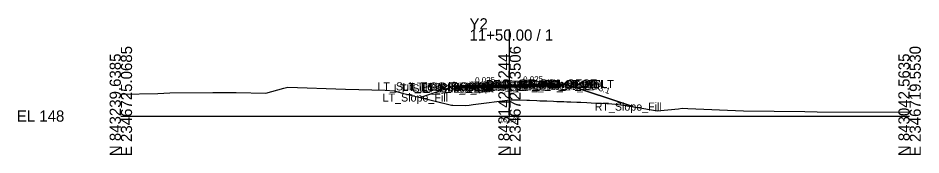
# Model space of a CAD drawing. Extents: x -26 to 2346977, y -10 to 843253.
# Drawn here: x -25.7 to 200, y 990.3 to 1024.5 of the extents above; entities that cross this region are included whole.
import ezdxf

# ---------------------------------------------------------------- set-up
doc = ezdxf.new("R2010")
doc.units = 0
for name, color, linetype in [('Default', 7, 'Continuous'), ('Exist Cross Section Cell', 7, 'Continuous'), ('Exist XS Center Line Elevation Label', 7, 'Continuous'), ('Exist XS Ground Line', 7, 'Continuous'), ('Prop CMT Pvmt Course 1', 7, 'Continuous'), ('Prop CMT Pvmt Course 2', 7, 'Continuous'), ('Prop CMT Pvmt Course 3', 7, 'Continuous'), ('Prop CMT Pvmt Surface', 7, 'Continuous'), ('Prop CMT Pvmt Surface Shoulder', 7, 'Continuous'), ('Prop CMT Shld Paved Course 1', 7, 'Continuous'), ('Prop CMT Shld Paved Course 2', 7, 'Continuous'), ('Prop CMT Shld Paved Course 3', 7, 'Continuous'), ('Prop CMT Slope Grass', 7, 'Continuous'), ('Prop CMT Subgrade Earthwork', 7, 'Continuous'), ('Prop XS Earthwork Shape', 7, 'Continuous'), ('Prop XS SE Text', 7, 'Continuous'), ('Prop XS Side Slope Text', 7, 'Continuous'), ('Scratch_Level_2', 7, 'Continuous')]:
    doc.layers.add(name, color=color, linetype=linetype)

msp = doc.modelspace()

# ---------------------------------------------------------------- linework, layer by layer
at = {"layer": 'Exist Cross Section Cell'}
for p, q in [((97.15, 1000), (97.15, 1021.61)), ((0, 1000), (97.15, 1000)), ((97.15, 1000), (197.15, 1000))]:
    msp.add_line(p, q, dxfattribs=at)
at = {"layer": 'Exist XS Ground Line'}
msp.add_lwpolyline([(0, 1005.45), (9.25, 1005.66), (12.21, 1005.79), (23.01, 1005.84), (25.23, 1005.85), (28.42, 1005.86), (28.84, 1005.85), (36.24, 1005.74), (40.77, 1006.94), (41.76, 1007.2), (56.12, 1006.7), (66.04, 1006.43), (68.3, 1006.28), (70.38, 1005.71), (82.67, 1002.74), (83.01, 1002.73), (86.27, 1002.64), (87.06, 1002.74), (88.1, 1002.87), (97.3, 1004.09), (98.05, 1004.08), (99.01, 1004.04), (99.61, 1004.02), (101.5, 1003.96), (102.18, 1003.93), (104, 1003.87), (104.77, 1003.84), (106.52, 1003.77), (108.15, 1003.71), (109.01, 1003.67), (110.05, 1003.64), (110.35, 1003.63), (110.77, 1003.61), (111.48, 1003.58), (112.44, 1003.54), (113.96, 1003.47), (115, 1003.43), (116.48, 1003.37), (117.58, 1003.31), (118.99, 1003.24), (120.17, 1003.19), (121.48, 1003.12), (122.76, 1003.02), (123.65, 1002.98), (124.94, 1002.8), (127.61, 1002.42), (130.75, 1001.93), (134.09, 1001.33), (139.37, 1001.84), (140.31, 1001.94), (141.72, 1001.88), (155.66, 1001.33), (171, 1001.14), (174.07, 1001.09), (197.15, 1000.98)], dxfattribs=at)
at = {"layer": 'Prop CMT Pvmt Course 1'}
for p, q in [((97.15, 1007.83), (85.15, 1007.53)), ((85.15, 1007.28), (97.15, 1007.58)), ((85.15, 1007.53), (85.15, 1007.28)), ((97.15, 1007.83), (109.15, 1008.13)), ((109.15, 1007.88), (97.15, 1007.58)), ((97.15, 1007.58), (97.15, 1007.83)), ((97.15, 1007.58), (97.15, 1007.83)), ((97.15, 1007.58), (97.15, 1007.7)), ((97.15, 1007.7), (97.15, 1007.7)), ((97.15, 1007.7), (97.15, 1007.58)), ((97.15, 1007.58), (97.15, 1007.7)), ((97.15, 1007.7), (97.15, 1007.7)), ((97.15, 1007.7), (97.15, 1007.58)), ((97.15, 1007.58), (97.15, 1007.58)), ((97.15, 1007.58), (97.15, 1007.58)), ((109.15, 1008.13), (109.15, 1007.88))]:
    msp.add_line(p, q, dxfattribs=at)
at = {"layer": 'Prop CMT Pvmt Course 2'}
for p, q in [((85.15, 1007.28), (97.15, 1007.58)), ((97.15, 1007.58), (85.15, 1007.28)), ((85.15, 1007.28), (85.15, 1007.28)), ((109.15, 1007.88), (97.15, 1007.58)), ((97.15, 1007.58), (109.15, 1007.88)), ((97.15, 1007.58), (97.15, 1007.58)), ((97.15, 1007.58), (97.15, 1007.58)), ((109.15, 1007.88), (109.15, 1007.88))]:
    msp.add_line(p, q, dxfattribs=at)
at = {"layer": 'Prop CMT Pvmt Course 3'}
for p, q in [((97.15, 1007.58), (85.15, 1007.28)), ((85.15, 1007.28), (85.15, 1006.94)), ((85.15, 1006.94), (97.15, 1007.24)), ((97.15, 1007.58), (109.15, 1007.88)), ((97.15, 1007.24), (97.15, 1007.58)), ((97.15, 1007.24), (97.15, 1007.58)), ((109.15, 1007.54), (97.15, 1007.24)), ((109.15, 1007.88), (109.15, 1007.54))]:
    msp.add_line(p, q, dxfattribs=at)
at = {"layer": 'Prop CMT Pvmt Surface'}
for q in [(85.15, 1007.53), (109.15, 1008.13)]:
    msp.add_line((97.15, 1007.83), q, dxfattribs=at)
at = {"layer": 'Prop CMT Pvmt Surface Shoulder'}
for p, q in [((85.15, 1007.53), (85.15, 1007.53)), ((109.15, 1008.13), (109.15, 1008.13))]:
    msp.add_line(p, q, dxfattribs=at)
at = {"layer": 'Prop CMT Shld Paved Course 1'}
for p, q in [((85.15, 1007.53), (84.9, 1007.27)), ((84.9, 1007.27), (85.15, 1007.28)), ((85.15, 1007.53), (85.15, 1007.53)), ((85.15, 1007.28), (85.15, 1007.53)), ((109.15, 1008.13), (109.15, 1008.13)), ((109.15, 1008.13), (109.41, 1007.87)), ((109.15, 1007.88), (109.15, 1008.13)), ((109.41, 1007.87), (109.15, 1007.88))]:
    msp.add_line(p, q, dxfattribs=at)
at = {"layer": 'Prop CMT Shld Paved Course 2'}
for p, q in [((85.15, 1007.28), (84.9, 1007.27)), ((84.9, 1007.27), (85.15, 1007.28)), ((84.9, 1007.27), (84.9, 1007.27)), ((85.15, 1007.28), (85.15, 1007.28)), ((109.15, 1007.88), (109.41, 1007.87)), ((109.41, 1007.87), (109.15, 1007.88)), ((109.15, 1007.88), (109.15, 1007.88)), ((109.41, 1007.87), (109.41, 1007.87))]:
    msp.add_line(p, q, dxfattribs=at)
at = {"layer": 'Prop CMT Shld Paved Course 3'}
for p, q in [((84.4, 1007.26), (84.06, 1006.92)), ((84.06, 1006.92), (85.15, 1006.94)), ((84.9, 1007.27), (84.4, 1007.26)), ((85.15, 1007.28), (84.9, 1007.27)), ((85.15, 1006.94), (85.15, 1007.28)), ((109.15, 1007.88), (109.41, 1007.87)), ((109.15, 1007.54), (109.15, 1007.88)), ((110.25, 1007.52), (109.15, 1007.54)), ((109.41, 1007.87), (109.91, 1007.86)), ((109.91, 1007.86), (110.25, 1007.52))]:
    msp.add_line(p, q, dxfattribs=at)
at = {"layer": 'Prop CMT Slope Grass'}
for p, q in [((83.15, 1007.37), (74.91, 1004.62)), ((85.15, 1007.53), (83.15, 1007.37)), ((109.15, 1008.13), (111.15, 1007.97)), ((111.15, 1007.97), (127.96, 1002.36))]:
    msp.add_line(p, q, dxfattribs=at)
at = {"layer": 'Prop CMT Subgrade Earthwork'}
for p, q in [((84.06, 1006.92), (83.58, 1007.4)), ((85.15, 1006.94), (84.06, 1006.92)), ((97.15, 1007.24), (85.15, 1006.94)), ((97.15, 1007.24), (109.15, 1007.54)), ((109.15, 1007.54), (110.25, 1007.52)), ((110.25, 1007.52), (110.73, 1008))]:
    msp.add_line(p, q, dxfattribs=at)
at = {"layer": 'Prop XS Earthwork Shape'}
msp.add_lwpolyline([(84.06, 1006.92), (83.58, 1007.4), (83.15, 1007.37), (74.91, 1004.62), (82.67, 1002.74), (83.01, 1002.73), (86.27, 1002.64), (87.06, 1002.74), (88.1, 1002.87), (97.3, 1004.09), (98.05, 1004.08), (99.01, 1004.04), (99.61, 1004.02), (101.5, 1003.96), (102.18, 1003.93), (104, 1003.87), (104.77, 1003.84), (106.52, 1003.77), (108.15, 1003.71), (109.01, 1003.67), (110.05, 1003.64), (110.35, 1003.63), (110.77, 1003.61), (111.48, 1003.58), (112.44, 1003.54), (113.96, 1003.47), (115, 1003.43), (116.48, 1003.37), (117.58, 1003.31), (118.99, 1003.24), (120.17, 1003.19), (121.48, 1003.12), (122.76, 1003.02), (123.65, 1002.98), (124.94, 1002.8), (127.61, 1002.42), (127.96, 1002.36), (111.15, 1007.97), (110.73, 1008), (110.25, 1007.52), (109.15, 1007.54), (97.15, 1007.24), (85.15, 1006.94)], close=True, dxfattribs=at)

# ---------------------------------------------------------------- texts
at = {"layer": 'Default'}
msp.add_text('-', height=0.0001, dxfattribs=at).set_placement((0, 1000))
at = {"layer": 'Exist Cross Section Cell'}
for s, p in [('Y2', (87.15, 1021.61)), ('11+50.00 / 1', (87.15, 1018.81)), ('EL 148', (-26, 998.6))]:
    msp.add_text(s, height=2.8, dxfattribs=at).set_placement(p)
for s, p in [('E 2346725.0685', (2.8, 990)), ('E 2346722.3506', (99.95, 990)), ('E 2346719.5530', (199.95, 990)), ('N 843239.6385', (0, 990)), ('N 843142.5244', (97.15, 990)), ('N 843042.5635', (197.15, 990))]:
    msp.add_text(s, height=2.8, rotation=90, dxfattribs=at).set_placement(p)
at = {"layer": 'Exist XS Center Line Elevation Label'}
msp.add_text('152.07', height=1.2, dxfattribs=at).set_placement((94.66, 998.47))
at = {"layer": 'Prop XS SE Text'}
for p in [(88.57, 1008.17), (100.57, 1008.37)]:
    msp.add_text('0.025', height=1.5, rotation=1.4321, dxfattribs=at).set_placement(p)
at = {"layer": 'Prop XS Side Slope Text'}
for rotation, p in [(18.4332, (78.48, 1006.1)), (341.5668, (119.34, 1006.37))]:
    msp.add_text('3:1', height=1.5, rotation=rotation, dxfattribs=at).set_placement(p)
at = {"layer": 'Scratch_Level_2'}
for s, p in [('RT_Sub_Trench_Out_DLT', (91.25, 1007)), ('PV1_PGL', (91.62, 1006.83)), ('RT_PS3_Shelf_Out', (95.84, 1006.86)), ('RT_PV3_OEOT', (99.28, 1006.88)), ('RT_PV2_OEOT', (99.28, 1006.88)), ('RT_PS3_OEOP', (99.6, 1006.87)), ('RT_PS2_OEOP', (99.6, 1006.87)), ('RT_PV1_OEOT', (99.85, 1007.13)), ('RT_PS1_OEOP', (99.91, 1007.13)), ('RT_GS_OS_CTL', (100.48, 1006.97)), ('LT_Sub_Trench_Out_DLT', (64.14, 1006.4)), ('LT_Sub_Trench_Out', (68.26, 1005.92)), ('LT_PS3_Shelf_Out', (70.38, 1006.26)), ('LT_GS_OS_CTL', (72.52, 1006.37)), ('LT_PS3_OEOP', (75.13, 1006.27)), ('LT_PS2_OEOP', (75.13, 1006.27)), ('LT_Sub_OEOT', (75.23, 1005.94)), ('LT_PV3_OEOT', (75.33, 1006.28)), ('LT_PV2_OEOT', (75.33, 1006.28)), ('LT_PV1_OEOT', (75.89, 1006.53)), ('LT_PS1_OEOP', (75.96, 1006.53)), ('RT_Sub_OEEOP', (86.32, 1006.24)), ('LT_Sub_OEEOP', (86.36, 1006.24)), ('RT_PV2_OEEOP', (86.41, 1006.58)), ('RT_PV3_OEEOP', (86.41, 1006.58)), ('LT_PV2_OEEOP', (86.46, 1006.58)), ('LT_PV3_OEEOP', (86.46, 1006.58)), ('RT_PV1_OEEOP', (86.98, 1006.7)), ('LT_PV1_OEEOP', (87.03, 1006.7)), ('RT_PV2_IEEOP', (87.06, 1006.58)), ('LT_PV2_IEEOP', (87.1, 1006.58)), ('RT_PV1_IEEOP', (87.62, 1006.7)), ('LT_PV1_IEEOP', (87.67, 1006.7)), ('PV2_PGL', (91.06, 1006.58)), ('RT_Sub_Trench_Out', (94.4, 1006.52)), ('RT_Sub_OEOT', (99.18, 1006.54)), ('LT_Slope_Fill', (65.43, 1003.62)), ('RT_Slope_Fill', (118.43, 1001.36))]:
    msp.add_text(s, height=2, dxfattribs=at).set_placement(p)

doc.saveas('drawing.dxf')
